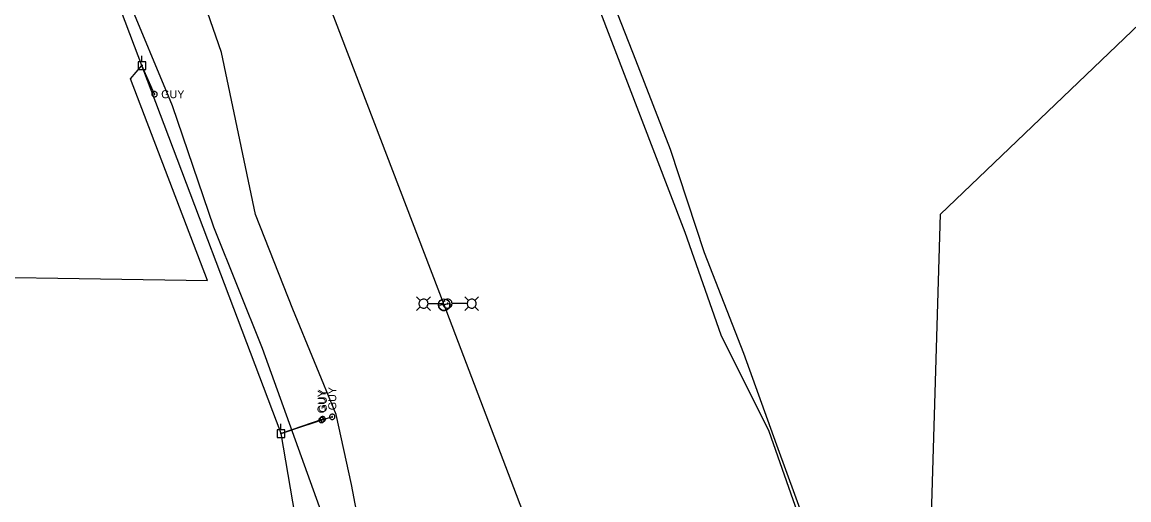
# Model space of a CAD drawing. Extents: x 596028 to 606371, y 330010 to 403088.
# Drawn here: x 603307 to 603840, y 350943 to 351173 of the extents above; entities that cross this region are included whole.
import ezdxf

# ---------------------------------------------------------------- set-up
doc = ezdxf.new("R2010")
doc.units = 0
for name, color, linetype in [('E_FTMS_Conduit', 7, 'Continuous'), ('E_LTG', 7, 'Continuous'), ('E_LTG_CID', 7, 'Continuous'), ('E_UTL_E_UG', 7, 'Continuous'), ('E_UTL_EGuyWire', 7, 'Continuous'), ('E_UTL_EPowerPole', 7, 'Continuous'), ('E_UTL_FO_UG_QWEST', 7, 'Continuous'), ('E_UTL_Overhead', 7, 'Continuous'), ('E_UTL_T_UG', 7, 'Continuous'), ('E_UTL_W_UG', 7, 'Continuous')]:
    doc.layers.add(name, color=color, linetype=linetype)

# ---------------------------------------------------------------- blocks, each defined once
blk = doc.blocks.new('_U272')
at = {"layer": 'E_LTG'}
blk.add_lwpolyline([(0.001, -0.171), (0.001, 0.172)], dxfattribs=at)
blk.add_circle((0.001, 0), 0.171, dxfattribs=at)
blk.add_arc((0.001, 0), 0.171, 90, 270, dxfattribs=at)
blk.add_text('L', height=0.108, dxfattribs=at).set_placement((0.066, -0.042))

msp = doc.modelspace()

# ---------------------------------------------------------------- linework, layer by layer
at = {"layer": 'E_FTMS_Conduit'}
msp.add_lwpolyline([(603609.26, 350547.29), (603590.93, 350587.57), (603576.33, 350628.92), (603565.39, 350659.37), (603552.92, 350690.81), (603529.87, 350755.72), (603524.01, 350769.33), (603507.4, 350805.93), (603488.24, 350844.06), (603483.2, 350870.26), (603473.58, 350908.61), (603465.8, 350950.07), (603458.47, 350983.69), (603437.61, 351034.41), (603419.58, 351080.05), (603403.21, 351158.05), (603376.31, 351235.86), (603345.63, 351318.27), (603314.78, 351397.25), (603283.64, 351476.72)], dxfattribs=at)
at = {"layer": 'E_LTG'}
for points in [[(603498.88, 351038.62), (603497.11, 351040.39)], [(603501.93, 351038.62), (603503.71, 351040.39)], [(603522.06, 351038.62), (603520.28, 351040.39)], [(603525.1, 351038.62), (603526.88, 351040.39)], [(603498.88, 351035.57), (603497.11, 351033.79)], [(603502.58, 351037.09), (603502.55, 351037.51), (603502.43, 351037.9), (603502.24, 351038.27), (603501.98, 351038.6), (603501.67, 351038.87), (603501.31, 351039.07), (603500.92, 351039.21), (603500.51, 351039.27), (603500.1, 351039.25), (603499.7, 351039.15), (603499.32, 351038.98), (603498.98, 351038.74), (603498.7, 351038.44), (603498.48, 351038.09), (603498.32, 351037.71), (603498.24, 351037.3), (603498.24, 351036.89), (603498.32, 351036.48), (603498.48, 351036.1), (603498.7, 351035.75), (603498.98, 351035.45), (603499.32, 351035.21), (603499.7, 351035.04), (603500.1, 351034.94), (603500.51, 351034.92), (603500.92, 351034.98), (603501.31, 351035.12), (603501.67, 351035.32), (603501.98, 351035.59), (603502.24, 351035.92), (603502.43, 351036.29), (603502.55, 351036.68), (603502.58, 351037.09)], [(603501.93, 351035.57), (603503.71, 351033.79)], [(603502.62, 351037.09), (603509.8, 351037.09)], [(603514.15, 351037.09), (603514.11, 351037.51), (603513.99, 351037.9), (603513.81, 351038.27), (603513.55, 351038.6), (603513.24, 351038.87), (603512.88, 351039.07), (603512.49, 351039.21), (603512.08, 351039.27), (603511.67, 351039.25), (603511.26, 351039.15), (603510.89, 351038.98), (603510.55, 351038.74), (603510.26, 351038.44), (603510.04, 351038.09), (603509.89, 351037.71), (603509.81, 351037.3), (603509.81, 351036.89), (603509.89, 351036.48), (603510.04, 351036.1), (603510.26, 351035.75), (603510.55, 351035.45), (603510.89, 351035.21), (603511.26, 351035.04), (603511.67, 351034.94), (603512.08, 351034.92), (603512.49, 351034.98), (603512.88, 351035.12), (603513.24, 351035.32), (603513.55, 351035.59), (603513.81, 351035.92), (603513.99, 351036.29), (603514.11, 351036.68), (603514.15, 351037.09)], [(603512.14, 351037.09), (603512.14, 351037.13), (603512.13, 351037.16), (603512.11, 351037.18), (603512.1, 351037.21), (603512.07, 351037.23), (603512.04, 351037.25), (603512.01, 351037.26), (603511.98, 351037.26), (603511.95, 351037.26), (603511.92, 351037.25), (603511.89, 351037.24), (603511.87, 351037.22), (603511.84, 351037.2), (603511.83, 351037.17), (603511.82, 351037.14), (603511.81, 351037.11), (603511.81, 351037.08), (603511.82, 351037.05), (603511.83, 351037.02), (603511.84, 351036.99), (603511.87, 351036.97), (603511.89, 351036.95), (603511.92, 351036.94), (603511.95, 351036.93), (603511.98, 351036.93), (603512.01, 351036.93), (603512.04, 351036.94), (603512.07, 351036.96), (603512.1, 351036.98), (603512.11, 351037), (603512.13, 351037.03), (603512.14, 351037.06), (603512.14, 351037.09)], [(603521.37, 351037.09), (603514.19, 351037.09)], [(603522.06, 351035.57), (603520.28, 351033.79)], [(603525.75, 351037.09), (603525.71, 351037.51), (603525.6, 351037.9), (603525.41, 351038.27), (603525.15, 351038.6), (603524.84, 351038.87), (603524.48, 351039.07), (603524.09, 351039.21), (603523.68, 351039.27), (603523.27, 351039.25), (603522.87, 351039.15), (603522.49, 351038.98), (603522.15, 351038.74), (603521.87, 351038.44), (603521.64, 351038.09), (603521.49, 351037.71), (603521.41, 351037.3), (603521.41, 351036.89), (603521.49, 351036.48), (603521.64, 351036.1), (603521.87, 351035.75), (603522.15, 351035.45), (603522.49, 351035.21), (603522.87, 351035.04), (603523.27, 351034.94), (603523.68, 351034.92), (603524.09, 351034.98), (603524.48, 351035.12), (603524.84, 351035.32), (603525.15, 351035.59), (603525.41, 351035.92), (603525.6, 351036.29), (603525.71, 351036.68), (603525.75, 351037.09)], [(603525.1, 351035.57), (603526.88, 351033.79)]]:
    msp.add_lwpolyline(points, dxfattribs=at)
at = {"layer": 'E_LTG_CID'}
for points in [[(604318.05, 348339.7), (604287.36, 348606.91), (604242.16, 348872.6), (604188.57, 349120.13), (604125.01, 349362.84), (604050.82, 349602.08), (604014.23, 349708.06), (603966.43, 349837.54), (603869.82, 350091.09), (603838.85, 350172.22), (603784.41, 350315.72), (603699.29, 350539.43), (603613.87, 350764.2), (603510.34, 351036.54), (603442.84, 351213.06), (603357.76, 351436.96)], [(603510.34, 351036.54), (603511.97, 351037.09)]]:
    msp.add_lwpolyline(points, dxfattribs=at)
at = {"layer": 'E_UTL_E_UG'}
for points in [[(603396.51, 351048.24), (603359.52, 351145.34), (603365.01, 351151.67)], [(603067.06, 351053.35), (603396.51, 351048.24)]]:
    msp.add_lwpolyline(points, dxfattribs=at)
at = {"layer": 'E_UTL_EGuyWire'}
for p, q in [((603371.06, 351137.9), (603365.01, 351151.67)), ((603456.52, 350982.58), (603431.88, 350974.54)), ((603451.95, 350981.45), (603431.88, 350974.54)), ((603431.88, 350974.54), (603451.37, 350981.09))]:
    msp.add_line(p, q, dxfattribs=at)
for points in [[(603372.34, 351137.9), (603372.32, 351138.14), (603372.25, 351138.38), (603372.13, 351138.59), (603371.98, 351138.79), (603371.8, 351138.95), (603371.59, 351139.07), (603371.36, 351139.15), (603371.12, 351139.18), (603370.87, 351139.17), (603370.64, 351139.11), (603370.41, 351139.01), (603370.21, 351138.87), (603370.05, 351138.69), (603369.91, 351138.49), (603369.82, 351138.26), (603369.78, 351138.02), (603369.78, 351137.78), (603369.82, 351137.54), (603369.91, 351137.31), (603370.05, 351137.11), (603370.21, 351136.93), (603370.41, 351136.79), (603370.64, 351136.69), (603370.87, 351136.63), (603371.12, 351136.62), (603371.36, 351136.65), (603371.59, 351136.73), (603371.8, 351136.86), (603371.98, 351137.02), (603372.13, 351137.21), (603372.25, 351137.42), (603372.32, 351137.66), (603372.34, 351137.9)], [(603371.22, 351137.9), (603371.21, 351137.93), (603371.2, 351137.96), (603371.19, 351137.99), (603371.17, 351138.01), (603371.15, 351138.03), (603371.12, 351138.05), (603371.09, 351138.06), (603371.06, 351138.06), (603371.03, 351138.06), (603371, 351138.05), (603370.97, 351138.04), (603370.95, 351138.02), (603370.93, 351138), (603370.91, 351137.97), (603370.9, 351137.95), (603370.9, 351137.92), (603370.9, 351137.89), (603370.9, 351137.86), (603370.91, 351137.83), (603370.93, 351137.8), (603370.95, 351137.78), (603370.97, 351137.76), (603371, 351137.75), (603371.03, 351137.74), (603371.06, 351137.74), (603371.09, 351137.75), (603371.12, 351137.76), (603371.15, 351137.77), (603371.17, 351137.79), (603371.19, 351137.81), (603371.2, 351137.84), (603371.21, 351137.87), (603371.22, 351137.9)], [(603451.37, 350982.37), (603451.13, 350982.35), (603450.89, 350982.28), (603450.68, 350982.16), (603450.48, 350982.01), (603450.32, 350981.83), (603450.2, 350981.62), (603450.12, 350981.39), (603450.09, 350981.15), (603450.1, 350980.9), (603450.16, 350980.67), (603450.26, 350980.44), (603450.4, 350980.24), (603450.58, 350980.08), (603450.78, 350979.94), (603451.01, 350979.85), (603451.25, 350979.81), (603451.49, 350979.81), (603451.73, 350979.85), (603451.96, 350979.94), (603452.16, 350980.08), (603452.34, 350980.24), (603452.48, 350980.44), (603452.58, 350980.67), (603452.64, 350980.9), (603452.65, 350981.15), (603452.62, 350981.39), (603452.54, 350981.62), (603452.41, 350981.83), (603452.25, 350982.01), (603452.06, 350982.16), (603451.85, 350982.28), (603451.61, 350982.35), (603451.37, 350982.37)], [(603451.95, 350982.73), (603451.71, 350982.71), (603451.47, 350982.64), (603451.26, 350982.52), (603451.07, 350982.37), (603450.91, 350982.19), (603450.78, 350981.98), (603450.7, 350981.75), (603450.67, 350981.51), (603450.68, 350981.26), (603450.74, 350981.03), (603450.84, 350980.8), (603450.98, 350980.6), (603451.16, 350980.44), (603451.36, 350980.3), (603451.59, 350980.21), (603451.83, 350980.17), (603452.07, 350980.17), (603452.31, 350980.21), (603452.54, 350980.3), (603452.74, 350980.44), (603452.92, 350980.6), (603453.06, 350980.8), (603453.16, 350981.03), (603453.22, 350981.26), (603453.23, 350981.51), (603453.2, 350981.75), (603453.12, 350981.98), (603453, 350982.19), (603452.84, 350982.37), (603452.64, 350982.52), (603452.43, 350982.64), (603452.19, 350982.71), (603451.95, 350982.73)], [(603451.37, 350981.25), (603451.34, 350981.24), (603451.31, 350981.23), (603451.28, 350981.22), (603451.26, 350981.2), (603451.24, 350981.18), (603451.22, 350981.15), (603451.21, 350981.12), (603451.21, 350981.09), (603451.21, 350981.06), (603451.22, 350981.03), (603451.23, 350981), (603451.25, 350980.98), (603451.27, 350980.96), (603451.3, 350980.94), (603451.32, 350980.93), (603451.35, 350980.93), (603451.38, 350980.93), (603451.41, 350980.93), (603451.44, 350980.94), (603451.47, 350980.96), (603451.49, 350980.98), (603451.51, 350981), (603451.52, 350981.03), (603451.53, 350981.06), (603451.53, 350981.09), (603451.52, 350981.12), (603451.51, 350981.15), (603451.5, 350981.18), (603451.48, 350981.2), (603451.46, 350981.22), (603451.43, 350981.23), (603451.4, 350981.24), (603451.37, 350981.25)], [(603451.95, 350981.61), (603451.92, 350981.6), (603451.89, 350981.59), (603451.86, 350981.58), (603451.84, 350981.56), (603451.82, 350981.54), (603451.81, 350981.51), (603451.8, 350981.48), (603451.79, 350981.45), (603451.79, 350981.42), (603451.8, 350981.39), (603451.81, 350981.36), (603451.83, 350981.34), (603451.85, 350981.32), (603451.88, 350981.3), (603451.91, 350981.29), (603451.94, 350981.29), (603451.97, 350981.29), (603452, 350981.29), (603452.02, 350981.3), (603452.05, 350981.32), (603452.07, 350981.34), (603452.09, 350981.36), (603452.1, 350981.39), (603452.11, 350981.42), (603452.11, 350981.45), (603452.11, 350981.48), (603452.1, 350981.51), (603452.08, 350981.54), (603452.06, 350981.56), (603452.04, 350981.58), (603452.01, 350981.59), (603451.98, 350981.6), (603451.95, 350981.61)], [(603456.52, 350983.87), (603456.28, 350983.84), (603456.04, 350983.77), (603455.83, 350983.66), (603455.63, 350983.51), (603455.47, 350983.33), (603455.35, 350983.12), (603455.27, 350982.88), (603455.24, 350982.64), (603455.25, 350982.4), (603455.31, 350982.16), (603455.41, 350981.94), (603455.55, 350981.74), (603455.73, 350981.57), (603455.93, 350981.44), (603456.16, 350981.35), (603456.4, 350981.3), (603456.64, 350981.3), (603456.88, 350981.35), (603457.11, 350981.44), (603457.31, 350981.57), (603457.49, 350981.74), (603457.63, 350981.94), (603457.73, 350982.16), (603457.79, 350982.4), (603457.8, 350982.64), (603457.77, 350982.88), (603457.69, 350983.12), (603457.57, 350983.33), (603457.41, 350983.51), (603457.21, 350983.66), (603457, 350983.77), (603456.76, 350983.84), (603456.52, 350983.87)], [(603456.52, 350982.74), (603456.49, 350982.74), (603456.46, 350982.73), (603456.43, 350982.72), (603456.41, 350982.7), (603456.39, 350982.68), (603456.37, 350982.65), (603456.36, 350982.62), (603456.36, 350982.59), (603456.36, 350982.56), (603456.37, 350982.53), (603456.38, 350982.5), (603456.4, 350982.48), (603456.42, 350982.46), (603456.45, 350982.44), (603456.47, 350982.43), (603456.5, 350982.42), (603456.54, 350982.42), (603456.57, 350982.43), (603456.59, 350982.44), (603456.62, 350982.46), (603456.64, 350982.48), (603456.66, 350982.5), (603456.67, 350982.53), (603456.68, 350982.56), (603456.68, 350982.59), (603456.68, 350982.62), (603456.67, 350982.65), (603456.65, 350982.68), (603456.63, 350982.7), (603456.61, 350982.72), (603456.58, 350982.73), (603456.55, 350982.74), (603456.52, 350982.74)]]:
    msp.add_lwpolyline(points, dxfattribs=at)
at = {"layer": 'E_UTL_EPowerPole'}
for points in [[(603366.82, 351153.52), (603363.13, 351153.52)], [(603363.13, 351153.52), (603363.13, 351149.83)], [(603365.25, 351151.67), (603365.24, 351151.72), (603365.23, 351151.76), (603365.21, 351151.8), (603365.18, 351151.84), (603365.15, 351151.87), (603365.11, 351151.89), (603365.07, 351151.91), (603365.02, 351151.91), (603364.98, 351151.91), (603364.93, 351151.9), (603364.89, 351151.88), (603364.85, 351151.85), (603364.82, 351151.82), (603364.8, 351151.78), (603364.78, 351151.74), (603364.77, 351151.7), (603364.77, 351151.65), (603364.78, 351151.61), (603364.8, 351151.56), (603364.82, 351151.53), (603364.85, 351151.49), (603364.89, 351151.47), (603364.93, 351151.45), (603364.98, 351151.44), (603365.02, 351151.44), (603365.07, 351151.44), (603365.11, 351151.46), (603365.15, 351151.48), (603365.18, 351151.51), (603365.21, 351151.55), (603365.23, 351151.59), (603365.24, 351151.63), (603365.25, 351151.67)], [(603364.98, 351153.52), (603364.98, 351156.43)], [(603366.82, 351149.83), (603366.82, 351153.52)], [(603363.13, 351149.83), (603366.82, 351149.83)], [(603433.7, 350976.38), (603430.01, 350976.38)], [(603430.01, 350976.38), (603430.01, 350972.69)], [(603431.85, 350976.38), (603431.85, 350979.29)], [(603433.7, 350972.69), (603433.7, 350976.38)], [(603430.01, 350972.69), (603433.7, 350972.69)], [(603432.12, 350974.54), (603432.12, 350974.58), (603432.11, 350974.62), (603432.08, 350974.66), (603432.06, 350974.7), (603432.02, 350974.73), (603431.98, 350974.75), (603431.94, 350974.77), (603431.9, 350974.77), (603431.85, 350974.77), (603431.81, 350974.76), (603431.76, 350974.74), (603431.73, 350974.72), (603431.7, 350974.68), (603431.67, 350974.64), (603431.66, 350974.6), (603431.65, 350974.56), (603431.65, 350974.51), (603431.66, 350974.47), (603431.67, 350974.43), (603431.7, 350974.39), (603431.73, 350974.35), (603431.76, 350974.33), (603431.81, 350974.31), (603431.85, 350974.3), (603431.9, 350974.3), (603431.94, 350974.3), (603431.98, 350974.32), (603432.02, 350974.34), (603432.06, 350974.37), (603432.08, 350974.41), (603432.11, 350974.45), (603432.12, 350974.49), (603432.12, 350974.54)]]:
    msp.add_lwpolyline(points, dxfattribs=at)
at = {"layer": 'E_UTL_FO_UG_QWEST'}
msp.add_lwpolyline([(603457.26, 350519.89), (603458.06, 350580.31), (603459.78, 350635.27), (603460.41, 350694.56), (603460.42, 350694.52), (603460.77, 350740.82), (603462.52, 350795.19), (603465.43, 350883.25), (603460.42, 350911.12), (603422.96, 351015.55), (603399.52, 351073.87), (603379.61, 351132.32), (603357.48, 351186), (603338.12, 351234.94), (603318.47, 351290.15), (603261.54, 351443.61)], dxfattribs=at)
at = {"layer": 'E_UTL_Overhead'}
msp.add_lwpolyline([(603468.46, 350246.59), (603449.86, 350441.98), (603456.5, 350830.83), (603431.88, 350974.54), (603298.9, 351326.49)], dxfattribs=at)
at = {"layer": 'E_UTL_T_UG'}
for points in [[(603697.35, 350875.17), (603695.97, 350887.71), (603683.55, 350927.48), (603666.68, 350975.49), (603643.57, 351021.93), (603626.19, 351071.29), (603577.12, 351199.32), (603609.14, 351233.94)], [(603704.58, 350873.02), (603699.95, 350886.22), (603688.96, 350917.97), (603670.36, 350968.89), (603654.5, 351013.15), (603635.58, 351061.48), (603619.18, 351111.24), (603602.55, 351154.33), (603585.57, 351197.86), (603601.34, 351220.63), (603623.32, 351223.76), (603638.74, 351226.02), (603705.22, 351228.11)]]:
    msp.add_lwpolyline(points, dxfattribs=at)
at = {"layer": 'E_UTL_W_UG'}
msp.add_lwpolyline([(603848.58, 350733.11), (603849.18, 350771.81), (603743.07, 350881.3), (603749.01, 351080.21), (603844.81, 351171.86), (604184.2, 351164.46)], dxfattribs=at)

# ---------------------------------------------------------------- block references
at = {"layer": 'E_LTG_CID', "xscale": 16.404166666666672, "yscale": 16.404166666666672, "rotation": 97.82095686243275}
msp.add_blockref('_U272', (603510.35, 351036.53), dxfattribs=at)

# ---------------------------------------------------------------- texts
at = {"layer": 'E_UTL_EGuyWire'}
msp.add_text('GUY', height=3.85, dxfattribs=at).set_placement((603374.26, 351135.98))
for p in [(603453.29, 350984.29), (603453.88, 350984.65), (603458.45, 350985.79)]:
    msp.add_text('GUY', height=3.85, rotation=90, dxfattribs=at).set_placement(p)

doc.saveas('drawing.dxf')
